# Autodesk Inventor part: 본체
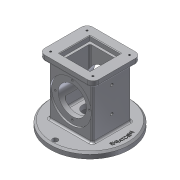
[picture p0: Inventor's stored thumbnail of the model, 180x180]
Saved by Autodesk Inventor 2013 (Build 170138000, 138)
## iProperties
Created: 2019-08
Part Number: 본체
Material: 알루미늄 6061
Document SubType Name: Modeling
Designer: Administrator
Density: 2.71 g/cm^3
Mass: 1073.97 g
Surface Area: 783.177 cm^2
Volume: 396.298 cm^3
Author: Administrator
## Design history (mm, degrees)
sketch "스케치1"
  geometry: L1 (33, 37)-(-33, 37); L2 (-33, 37)-(-33, -37); L3 (-33, -37)-(33, -37); L4 (33, -37)-(33, 37); L5 (33, 37)-(-33, -37); L6 (-33, 37)-(33, -37); 1 further point
  constraints: 12 end point, 2 midpoint, 2 parallel, 1 horizontal, 1 perpendicular
  dimensions: "d0" = 74 distance of L1.end L2.end; "d2" = 66 distance of L1.start L1.end
extrude "돌출1" new body sketch "스케치1" stored distance "d3" = 108; taper "d4" = 0 deg
sketch "스케치2"
  geometry: 2 further points
  constraints: 1 coincident
hole "구멍1" sketch "스케치2" at (54, 37) diameter "d5" = 48; stored, may be unused: countersink angle "d9" = 90 deg, drill point angle "d11" = 118 deg; dims "d6" = 6, "d7" = 70, "d8" = 3, "d10" = 48
sketch "스케치3"
  geometry: C1 r 35 at (0, 0) reference; 1 further point
  constraints: 1 horizontal alignment
  dimensions: "d12" = 29 distance of C1.centre point (-29, 0)
hole "구멍2" sketch "스케치3" at (-29, 0) diameter "d13" = 3.242; stored, may be unused: countersink angle "d17" = 90 deg, drill point angle "d19" = 118 deg; dims "d14" = 4, "d15" = 70, "d16" = 3, "d18" = 6
sketch "스케치4"
  geometry: C1 r 67.5 at (0, 0); 1 further point
  constraints: 1 centre point, 1 coincident
  dimensions: "d23" = 135 diameter of C1
extrude "돌출2" join sketch "스케치4" distance "d25" = 10; taper "d26" = 0 deg
sketch "스케치5"
  geometry: L1 (41, 46)-(-41, 46); L2 (-41, 46)-(-41, -46); L3 (-41, -46)-(41, -46); L4 (41, -46)-(41, 46); L5 (41, 46)-(-41, -46); L6 (-41, 46)-(41, -46); 1 further point
  constraints: 12 end point, 2 midpoint, 2 parallel, 1 horizontal, 1 perpendicular
  dimensions: "d27" = 92 distance between parallel lines of L1 L3; "d29" = 82 distance of L1.start L1.end
extrude "돌출3" join sketch "스케치5" distance "d30" = 10; taper "d31" = 0 deg
fillet "모깎기1" dims "d32" = 10
sketch "스케치6"
  geometry: A1 r 10 centre (-31, 36) between (-31, 46) and (-41, 36) reference; A2 r 10 centre (-31, -36) between (-41, -36) and (-31, -46) reference; A3 r 10 centre (31, -36) between (31, -46) and (41, -36) reference; A4 r 10 centre (31, 36) between (41, 36) and (31, 46) reference; 5 further points
  constraints: 4 coincident
hole "구멍3" sketch "스케치6" at (-31, -36), (31, -36), (-31, 36), (31, 36) diameter "d33" = 3.242; stored, may be unused: countersink angle "d37" = 90 deg, drill point angle "d39" = 118 deg; dims "d34" = 4, "d35" = 70, "d36" = 3, "d38" = 6
sketch "스케치7"
  geometry: L1 (26, 26)-(-26, 26); L2 (-26, 26)-(-26, -26); L3 (-26, -26)-(26, -26); L4 (26, -26)-(26, 26); L5 (26, 26)-(-26, -26); L6 (-26, 26)-(26, -26); 1 further point
  constraints: 12 end point, 2 midpoint, 2 parallel, 2 perpendicular, 1 horizontal
  dimensions: "d40" = 52 distance of L1.end L2.end
extrude "돌출4" cut sketch "스케치7" distance "d42" = 8; taper "d43" = 0 deg
sketch "스케치8"
  geometry: L1 (22, -22)-(-22, -22); L2 (-22, -22)-(-22, 22); L3 (-22, 22)-(22, 22); L4 (22, 22)-(22, -22); L5 (22, -22)-(-22, 22); L6 (-22, -22)-(22, 22); 1 further point
  constraints: 12 end point, 2 midpoint, 2 parallel, 2 perpendicular, 1 horizontal
  dimensions: "d44" = 44 distance of L2.end L3.end
extrude "돌출5" cut sketch "스케치8" distance "d46" = 74; taper "d47" = 0 deg
sketch "스케치10"
  geometry: L1 (-34.5, 10)-(100.5, 10) reference; 3 further points
  constraints: 2 vertical alignment
  dimensions: "d55" = 37 distance from line of point (33, -27) L1; "d56" = 43 distance of point (33, -70) point (33, -27)
fillet "모깎기2" dims "d64" = 3
fillet "모깎기3" dims "d65" = 3
fillet "모깎기4" dims "d66" = 3
chamfer "모따기1" distance "d79" = 3; stored, may be unused: second distance "d80" = 2, angle "d81" = 45 deg
sketch "스케치13"
  geometry: C1 r 64.5 at (0, 0) reference; 3 further points
  constraints: 2 horizontal alignment, 1 vertical alignment
  dimensions: "d82" = 59 distance of point (-59, 0) C1.centre; "d83" = 59 distance of point (0, -59) C1.centre; "d84" = 59 distance of point (59, 0) C1.centre
hole "구멍7" sketch "스케치13" at (-59, 0), (0, -59), (59, 0) diameter "d85" = 9; stored, may be unused: countersink angle "d89" = 90 deg, drill point angle "d91" = 0 deg; dims "d86" = 25, "d87" = 50, "d88" = 18, "d90" = 6
sketch "스케치14"
  geometry: C1 r 4.5 at (-59, 0) reference; C2 r 64.5 at (0, 0) reference; 1 further point
  constraints: 1 coincident, 1 horizontal alignment, 2 other
feature "엠보싱2" sketch "스케치14" dims "d0" = 74, "d2" = 66, "d20" = 40, "d21" = 360 deg, "d92" = 0.5, "d93" = 0
chamfer "모따기2" distance "d94" = 1; stored, may be unused: second distance "d95" = 2, angle "d96" = 45 deg
fillet "모깎기6" dims "d98" = 3
fillet "모깎기7" dims "d99" = 3
sketch "스케치15"
  geometry: C1 r 67.5 at (0, 0) reference; 1 further point
  constraints: 1 coincident
hole "구멍8" sketch "스케치15" at (0, 0) diameter "d100" = 25; stored, may be unused: countersink angle "d104" = 90 deg, drill point angle "d106" = 0 deg; dims "d101" = 25, "d102" = 50, "d103" = 18, "d105" = 6
fillet "모깎기8" dims "d107" = 3
hole "구멍9" sketch "스케치10" diameter "d108" = 4.917; stored, may be unused: countersink angle "d112" = 90 deg, drill point angle "d114" = 0 deg; dims "d109" = 25, "d110" = 50, "d111" = 18, "d113" = 30
node "솔리드1"
pattern_circular "원형 패턴1" dims angle "d21" = 360 deg
mirror "대칭1"
